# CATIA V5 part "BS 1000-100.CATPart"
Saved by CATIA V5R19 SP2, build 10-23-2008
Part number: BS 1000-100
Bounding box of the stored display mesh (mm): x -24.865 to 24.865, y -24.997 to 24.997, z 0 to 238
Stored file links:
  C:\Users\Bora\Desktop\3D Katı model\BS serisi\BS 1000\BS 1000-100.CATPart
  C:\Program Files\Dassault Systemes\B19\intel_a\reffiles\standard\MetricThickPitch.txt
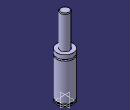
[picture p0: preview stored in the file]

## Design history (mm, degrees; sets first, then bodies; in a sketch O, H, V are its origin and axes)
Body1 (main body)
  Sketch1 on yz-plane, origin (0, 0, 0), H (0, 1, 0), V (0, 0, 1)
    point P2 (14, 236)
    line L1 (14, 236) -> (14, 137)
    point P3 (25, 124.5)
    line L2 (25, 137) -> (25, 124.5)
    point P6 (25, 120.5)
    line L3 (25, 120.5) -> (25, 7.5)
    line L4 (25, 4) -> (25, 0)
    point P9 (25, 120.5)
    point P10 (25, 124.5)
    arc A1 centre (25, 122.5) radius 2 from (25, 124.5) to (25, 120.5) ccw
    point P12 (14, 236)
    arc A2 centre (12, 236) radius 2 from (14, 236) to (12, 238) ccw
    point P13 (22.5, 4)
    point P14 (22.5, 4)
    line L5 (22.5, 7.5) -> (22.5, 4)
    line L6 (12, 238) -> (0, 238)
    point P16 (0, 238)
    line L7 (14, 137) -> (25, 137)
    line L8 (0, 0) -> (25, 0)
    line L9 (22.5, 4) -> (25, 4)
    line L10 (22.5, 7.5) -> (25, 7.5)
    coincidence: P16 V, P2 P12, P3 P10, P6 P9, P13 P14
    tangency: L6 A2
    horizontal: L7 H, L8 H, L9 H, L10 H
  Shaft1: profile Sketch1, axis Sketch1.V, angle 360
  Sketch2 on face of Shaft1 from Sketch1.L8, origin (0, 0, 0), H (1, 0, 0), V (0, -1, 0)
    point P1 (10, 0)
    distance P1 V = 10
  Hole1: placed by Sketch2, at (10, 0, 0) direction (0, 0, 1), diameter 6.647, depth 6, threaded "M8", thread diameter 8, thread depth 6, pitch 1.25
  CircPattern1: of Hole1, instances 2, angular step 180, axis from xy-plane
